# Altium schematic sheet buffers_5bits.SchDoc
size A4
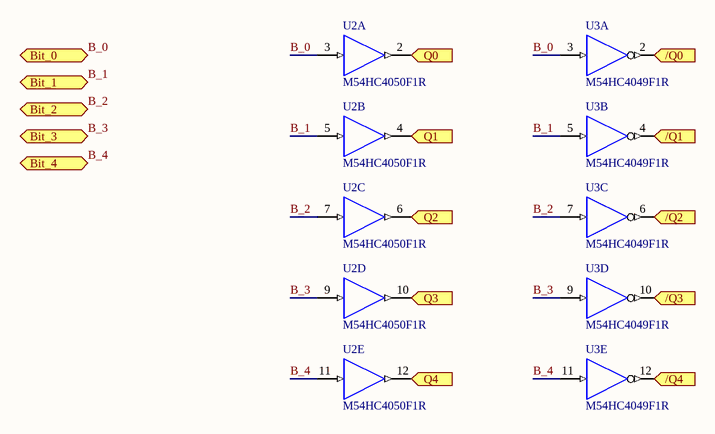
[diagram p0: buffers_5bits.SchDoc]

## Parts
U2  M54HC4050F1R  [DIP16]  (parts A,B,C,D,E of 6)
U3  M54HC4049F1R  [DIP16]  (parts A,B,C,D,E of 6)

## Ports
/Q0 (out), /Q1 (out), /Q2 (out), /Q3 (out), /Q4 (out), Bit_0 (in), Bit_1 (in), Bit_2 (in), Bit_3 (in), Bit_4 (in), Q0 (out), Q1 (out), Q2 (out), Q3 (out), Q4 (out)

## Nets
GND: U2.8(GND) U3.8(GND)
VCC: U2.1(VCC) U3.1(VCC)
/Q0: U3.2(Y) ; port /Q0
/Q1: U3.4(Y) ; port /Q1
/Q2: U3.6(Y) ; port /Q2
/Q3: U3.10(Y) ; port /Q3
/Q4: U3.12(Y) ; port /Q4
B_0: U2.3(A) U3.3(A) ; port Bit_0
B_1: U2.5(A) U3.5(A) ; port Bit_1
B_2: U2.7(A) U3.7(A) ; port Bit_2
B_3: U2.9(A) U3.9(A) ; port Bit_3
B_4: U2.11(A) U3.11(A) ; port Bit_4
Q0: U2.2(Y) ; port Q0
Q1: U2.4(Y) ; port Q1
Q2: U2.6(Y) ; port Q2
Q3: U2.10(Y) ; port Q3
Q4: U2.12(Y) ; port Q4

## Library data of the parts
U2 = M54HC4050F1R: Hex Buffer/Converter Non-Inverting; Note: Pins 13 and 16 are not connected and not drawn.
U3 = M54HC4049F1R: Hex Buffer/Converter Invertering; Note: Pins 13 and 16 are not connected and not drawn.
